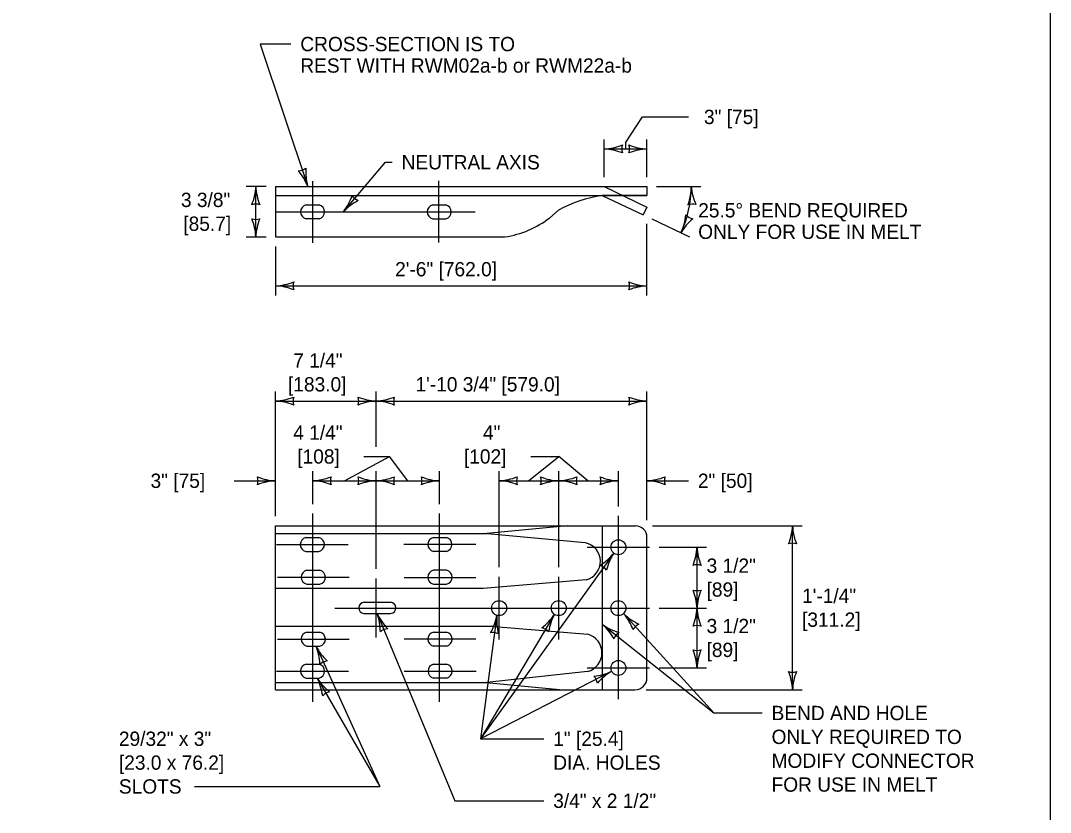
# Model space of a CAD drawing. Extents: x 49991.4 to 50021, y 49987.6 to 50011.4.
# Drawn here: x 50004.296 to 50008.615, y 50002.547 to 50005.867 of the extents above; entities that cross this region are included whole.
import ezdxf

# ---------------------------------------------------------------- set-up
doc = ezdxf.new("R2010")
doc.units = 0
for name, color, linetype in [('Level 1', 7, 'Continuous'), ('Level 2', 7, 'Continuous'), ('Level 3', 7, 'Continuous'), ('Level 4', 7, 'Continuous'), ('Level 5', 7, 'Continuous')]:
    doc.layers.add(name, color=color, linetype=linetype)

msp = doc.modelspace()

# ---------------------------------------------------------------- linework, layer by layer
at = {"layer": 'Level 1'}
for p, q in [((50005.3649, 50005.1705), (50006.9227, 50005.1705)), ((50005.3649, 50005.1705), (50005.3649, 50004.9596)), ((50006.9227, 50005.1705), (50006.9227, 50005.134)), ((50006.9227, 50005.134), (50006.7352, 50005.134)), ((50005.4929, 50005.0942), (50005.5474, 50005.0942)), ((50006.0241, 50005.0943), (50006.0787, 50005.0943)), ((50006.5147, 50005.0402), (50006.551, 50005.0713)), ((50005.5476, 50005.0356), (50005.4927, 50005.0356)), ((50006.024, 50005.0357), (50006.0788, 50005.0357)), ((50005.3649, 50004.9596), (50006.327, 50004.9596)), ((50005.3651, 50003.0612), (50005.3651, 50003.7485)), ((50005.3651, 50003.7485), (50006.8742, 50003.7485)), ((50006.5889, 50003.7485), (50006.2508, 50003.7166)), ((50005.3651, 50003.7166), (50006.2508, 50003.7166)), ((50005.492, 50003.6994), (50005.5465, 50003.6994)), ((50006.0268, 50003.6995), (50006.0267, 50003.6995)), ((50006.0267, 50003.6995), (50006.0814, 50003.6995)), ((50006.6641, 50003.6776), (50006.2388, 50003.7166)), ((50006.9227, 50003.1115), (50006.9227, 50003.7)), ((50005.4918, 50003.6408), (50005.5467, 50003.6408)), ((50006.0815, 50003.6409), (50006.0267, 50003.6409)), ((50005.4961, 50003.5619), (50005.5506, 50003.5619)), ((50006.0819, 50003.562), (50006.0272, 50003.562)), ((50006.2352, 50003.4858), (50005.3651, 50003.4858)), ((50005.4959, 50003.5033), (50005.5508, 50003.5033)), ((50006.0272, 50003.5034), (50006.082, 50003.5034)), ((50006.6677, 50003.5213), (50006.2352, 50003.4858)), ((50005.7369, 50003.4276), (50005.8463, 50003.4276)), ((50005.7356, 50003.3808), (50005.8475, 50003.3808)), ((50006.2836, 50003.3257), (50005.3651, 50003.3257)), ((50006.2836, 50003.3257), (50006.6741, 50003.2936)), ((50005.4961, 50003.3026), (50005.5506, 50003.3026)), ((50006.0272, 50003.3027), (50006.0819, 50003.3027)), ((50005.4959, 50003.244), (50005.5508, 50003.244)), ((50006.082, 50003.2441), (50006.0272, 50003.2441)), ((50006.0272, 50003.2441), (50006.0273, 50003.2441)), ((50005.4928, 50003.1685), (50005.5475, 50003.1685)), ((50006.0277, 50003.1684), (50006.0277, 50003.1684)), ((50006.0277, 50003.1684), (50006.0823, 50003.1684)), ((50006.6738, 50003.1373), (50006.2508, 50003.0916)), ((50005.4927, 50003.1099), (50005.5475, 50003.1099)), ((50006.0824, 50003.1098), (50006.0275, 50003.1098)), ((50005.3651, 50003.0916), (50006.2508, 50003.0916)), ((50005.3651, 50003.0612), (50006.8724, 50003.0612)), ((50006.5561, 50003.0612), (50006.2341, 50003.0916))]:
    msp.add_line(p, q, dxfattribs=at)
msp.add_lwpolyline([(50008.6146, 50011.2628), (50000.3356, 50011.2628), (50000.3356, 50000.0624), (50008.6146, 50000.0624)], close=True, dxfattribs=at)
for centre in [(50006.8026, 50003.6586), (50006.3026, 50003.4032), (50006.5526, 50003.4032), (50006.8026, 50003.4032), (50006.8026, 50003.1526)]:
    msp.add_circle(centre, 0.0313, dxfattribs=at)
for centre, radius, start, end in [((50006.8256, 50004.5662), 0.5749, 99.0478, 118.5325), ((50005.4994, 50005.0649), 0.03, 102.6034, 256.9962), ((50005.5408, 50005.0649), 0.03, 283.0068, 77.3935), ((50006.0307, 50005.065), 0.03, 102.7122, 257.1026), ((50006.0721, 50005.065), 0.03, 282.9005, 77.2847), ((50006.2644, 50005.3642), 0.4094, 278.786, 307.682), ((50006.8742, 50003.7), 0.0485, 0, 90), ((50005.4985, 50003.6701), 0.03, 102.6034, 256.9962), ((50005.5399, 50003.6701), 0.03, 283.0068, 77.3935), ((50006.0334, 50003.6702), 0.03, 102.7122, 257.1026), ((50006.0748, 50003.6702), 0.03, 282.9005, 77.2847), ((50006.647, 50003.599), 0.0804, 284.9666, 77.7099), ((50005.5026, 50003.5326), 0.03, 102.6034, 256.9962), ((50005.544, 50003.5326), 0.03, 283.0068, 77.3935), ((50006.0339, 50003.5327), 0.03, 102.7122, 257.1026), ((50006.0753, 50003.5327), 0.03, 282.9005, 77.2847), ((50005.7369, 50003.4042), 0.0234, 89.9951, 266.7585), ((50005.8463, 50003.4042), 0.0234, 272.9074, 89.9976), ((50005.5026, 50003.2733), 0.03, 102.6034, 256.9962), ((50005.544, 50003.2733), 0.03, 283.0068, 77.3935), ((50006.0339, 50003.2734), 0.03, 102.7122, 257.1026), ((50006.0753, 50003.2734), 0.03, 282.9005, 77.2847), ((50006.6528, 50003.2155), 0.081, 285.0418, 74.706), ((50005.4994, 50003.1392), 0.03, 102.7902, 257.18), ((50005.5408, 50003.1392), 0.03, 282.8231, 77.2067), ((50006.0343, 50003.1391), 0.03, 102.6821, 257.073), ((50006.0757, 50003.1391), 0.03, 282.9301, 77.3148), ((50006.8724, 50003.1115), 0.0503, 270, 0)]:
    msp.add_arc(centre, radius, start, end, dxfattribs=at)
at = {"layer": 'Level 3'}
for p, q in [((50005.4287, 50005.7684), (50005.301, 50005.7684)), ((50005.301, 50005.7684), (50005.5002, 50005.1705)), ((50006.833, 50005.3544), (50006.9041, 50005.463)), ((50006.9041, 50005.463), (50007.0974, 50005.463)), ((50006.7433, 50005.2105), (50006.7433, 50005.3687)), ((50006.833, 50005.3544), (50006.833, 50005.3287)), ((50006.9227, 50005.2105), (50006.9227, 50005.3687)), ((50006.7433, 50005.3287), (50006.9227, 50005.3287)), ((50005.6496, 50005.065), (50005.8263, 50005.2729)), ((50005.8263, 50005.2729), (50005.8535, 50005.2729)), ((50005.3249, 50005.1705), (50005.2421, 50005.1705)), ((50005.2821, 50004.9597), (50005.2821, 50005.1705)), ((50006.9627, 50005.1705), (50007.1485, 50005.1705)), ((50006.9227, 50004.7144), (50006.9227, 50005.0153)), ((50006.9431, 50005.0349), (50007.1008, 50004.9597)), ((50005.2421, 50004.9597), (50005.3249, 50004.9597)), ((50005.3649, 50004.9196), (50005.3649, 50004.7144)), ((50005.3649, 50004.7544), (50006.9227, 50004.7544)), ((50005.3649, 50003.7885), (50005.3649, 50004.3117)), ((50005.787, 50004.0791), (50005.787, 50004.3117)), ((50006.9227, 50003.7717), (50006.9227, 50004.3117)), ((50005.3649, 50004.2717), (50005.787, 50004.2717)), ((50005.787, 50004.2717), (50006.9227, 50004.2717)), ((50005.6542, 50003.9373), (50005.8426, 50004.0391)), ((50005.7358, 50004.0391), (50005.8426, 50004.0391)), ((50005.9198, 50003.9373), (50005.8426, 50004.0391)), ((50006.4264, 50003.9373), (50006.5526, 50004.0391)), ((50006.4349, 50004.0391), (50006.5526, 50004.0391)), ((50006.6748, 50003.9373), (50006.5526, 50004.0391)), ((50005.5215, 50003.8394), (50005.5215, 50003.9773)), ((50005.787, 50003.5676), (50005.787, 50003.9773)), ((50006.0526, 50003.8395), (50006.0526, 50003.9773)), ((50006.3026, 50003.5745), (50006.3026, 50003.9773)), ((50006.5526, 50003.5745), (50006.5526, 50003.9773)), ((50006.8026, 50003.8299), (50006.8026, 50003.9773)), ((50005.1916, 50003.9373), (50005.3649, 50003.9373)), ((50005.5215, 50003.9373), (50005.787, 50003.9373)), ((50005.787, 50003.9373), (50006.0526, 50003.9373)), ((50006.3026, 50003.9373), (50006.5526, 50003.9373)), ((50006.5526, 50003.9373), (50006.8026, 50003.9373)), ((50006.9227, 50003.9373), (50007.0961, 50003.9373)), ((50006.9459, 50003.7485), (50007.573, 50003.7485)), ((50007.533, 50003.0612), (50007.533, 50003.7485)), ((50006.9739, 50003.6586), (50007.1725, 50003.6586)), ((50007.1325, 50003.404), (50007.1325, 50003.6586)), ((50006.7831, 50003.6341), (50006.2238, 50002.8556)), ((50006.9739, 50003.4032), (50007.1725, 50003.4032)), ((50007.1325, 50003.1526), (50007.1325, 50003.404)), ((50005.7907, 50003.3808), (50006.1171, 50002.5956)), ((50006.5344, 50003.3777), (50006.2238, 50002.8556)), ((50006.2935, 50003.3733), (50006.2238, 50002.8556)), ((50006.8247, 50003.3811), (50007.2032, 50002.9636)), ((50006.7352, 50003.3354), (50007.2032, 50002.9636)), ((50005.5347, 50003.244), (50005.8027, 50002.6556)), ((50006.7748, 50003.1383), (50006.2238, 50002.8556)), ((50006.9739, 50003.1526), (50007.1725, 50003.1526)), ((50005.5389, 50003.1099), (50005.8027, 50002.6556)), ((50006.9187, 50003.0612), (50007.573, 50003.0612)), ((50007.2032, 50002.9636), (50007.4051, 50002.9636)), ((50006.2238, 50002.8556), (50006.4894, 50002.8556)), ((50005.0246, 50002.6556), (50005.8027, 50002.6556)), ((50006.1171, 50002.5956), (50006.4894, 50002.5956))]:
    msp.add_line(p, q, dxfattribs=at)
for centre, radius, start, end in [((50006.7341, 50005.5508), 0.2223, 272.3605, 292.544), ((50006.8715, 50005.3287), 0.0548, 162.1388, 197.8612), ((50006.9319, 50005.5508), 0.2223, 247.456, 267.6395), ((50006.7945, 50005.3287), 0.0548, 342.1388, 17.8612), ((50006.7318, 50005.096), 0.233, 67.9228, 87.1727), ((50006.9342, 50005.096), 0.233, 92.8273, 112.0772), ((50005.4597, 50005.2921), 0.0548, 270.5738, 306.2961), ((50005.2831, 50005.086), 0.233, 21.2623, 40.5121), ((50005.7138, 50005.2321), 0.2223, 175.891, 196.0745), ((50005.06, 50005.1797), 0.2223, 337.456, 357.6395), ((50005.5148, 50005.182), 0.233, 182.8273, 202.0772), ((50006.6585, 50005.1705), 0.45, 334.5194, 0.0004), ((50006.8862, 50005.1719), 0.2223, 339.456, 359.6395), ((50007.3407, 50005.1901), 0.233, 184.8273, 204.0772), ((50005.4648, 50005.207), 0.233, 322.4652, 341.715), ((50005.7326, 50005.1627), 0.0548, 211.7767, 247.499), ((50005.2821, 50005.0423), 0.0548, 72.1388, 107.8612), ((50005.8129, 50004.9142), 0.2223, 117.0939, 137.2774), ((50007.113, 50005.0424), 0.0548, 74.1388, 109.8612), ((50006.8643, 50005.0731), 0.2223, 334.3605, 354.544), ((50007.1249, 50005.0901), 0.0548, 224.1388, 259.8612), ((50005.2821, 50005.0879), 0.0548, 252.1388, 287.8612), ((50005.0494, 50004.9482), 0.233, 2.8273, 22.0772), ((50005.5042, 50004.9505), 0.2223, 157.456, 177.6395), ((50007.2648, 50004.8575), 0.233, 129.9228, 149.1727), ((50005.3534, 50004.9871), 0.233, 272.8273, 292.0772), ((50005.3557, 50004.5323), 0.2223, 67.456, 87.6395), ((50005.4931, 50004.7544), 0.0548, 162.1388, 197.8612), ((50006.9319, 50004.9765), 0.2223, 247.456, 267.6395), ((50006.7945, 50004.7544), 0.0548, 342.1388, 17.8612), ((50006.9342, 50004.5217), 0.233, 92.8273, 112.0772), ((50005.3534, 50004.5044), 0.233, 272.8273, 292.0772), ((50005.3557, 50004.0496), 0.2223, 67.456, 87.6395), ((50005.4931, 50004.2717), 0.0548, 162.1388, 197.8612), ((50005.7962, 50004.4938), 0.2223, 247.456, 267.6395), ((50005.6588, 50004.2717), 0.0548, 342.1388, 17.8612), ((50005.7985, 50004.039), 0.233, 92.8273, 112.0772), ((50005.7755, 50004.5044), 0.233, 272.8273, 292.0772), ((50005.7778, 50004.0496), 0.2223, 67.456, 87.6395), ((50005.9152, 50004.2717), 0.0548, 162.1388, 197.8612), ((50006.9319, 50004.4938), 0.2223, 247.456, 267.6395), ((50006.7945, 50004.2717), 0.0548, 342.1388, 17.8612), ((50006.9342, 50004.039), 0.233, 92.8273, 112.0772), ((50005.3741, 50004.1594), 0.2223, 247.456, 267.6395), ((50005.2367, 50003.9373), 0.0548, 342.1388, 17.8612), ((50005.3764, 50003.7046), 0.233, 92.8273, 112.0772), ((50005.51, 50004.17), 0.233, 272.8273, 292.0772), ((50005.5123, 50003.7152), 0.2223, 67.456, 87.6395), ((50005.6497, 50003.9373), 0.0548, 162.1388, 197.8612), ((50005.7962, 50004.1594), 0.2223, 247.456, 267.6395), ((50005.6588, 50003.9373), 0.0548, 342.1388, 17.8612), ((50005.7985, 50003.7046), 0.233, 92.8273, 112.0772), ((50005.7755, 50004.17), 0.233, 272.8273, 292.0772), ((50005.7778, 50003.7152), 0.2223, 67.456, 87.6395), ((50005.9152, 50003.9373), 0.0548, 162.1388, 197.8612), ((50006.0618, 50004.1594), 0.2223, 247.456, 267.6395), ((50005.9244, 50003.9373), 0.0548, 342.1388, 17.8612), ((50006.0641, 50003.7046), 0.233, 92.8273, 112.0772), ((50006.2911, 50004.17), 0.233, 272.8273, 292.0772), ((50006.2934, 50003.7152), 0.2223, 67.456, 87.6395), ((50006.4308, 50003.9373), 0.0548, 162.1388, 197.8612), ((50006.5618, 50004.1594), 0.2223, 247.456, 267.6395), ((50006.4244, 50003.9373), 0.0548, 342.1388, 17.8612), ((50006.5641, 50003.7046), 0.233, 92.8273, 112.0772), ((50006.5411, 50004.17), 0.233, 272.8273, 292.0772), ((50006.5434, 50003.7152), 0.2223, 67.456, 87.6395), ((50006.6808, 50003.9373), 0.0548, 162.1388, 197.8612), ((50006.8118, 50004.1594), 0.2223, 247.456, 267.6395), ((50006.6744, 50003.9373), 0.0548, 342.1388, 17.8612), ((50006.8141, 50003.7046), 0.233, 92.8273, 112.0772), ((50006.9112, 50004.17), 0.233, 272.8273, 292.0772), ((50006.9135, 50003.7152), 0.2223, 67.456, 87.6395), ((50007.0509, 50003.9373), 0.0548, 162.1388, 197.8612), ((50007.3109, 50003.7577), 0.2223, 337.456, 357.6395), ((50007.7657, 50003.76), 0.233, 182.8273, 202.0772), ((50006.9104, 50003.6678), 0.2223, 337.456, 357.6395), ((50007.3652, 50003.6701), 0.233, 182.8273, 202.0772), ((50007.533, 50003.6203), 0.0548, 72.1388, 107.8612), ((50006.6073, 50003.7702), 0.2223, 302.0762, 322.2597), ((50006.9795, 50003.5087), 0.233, 147.4475, 166.6974), ((50006.7089, 50003.5296), 0.0548, 36.759, 72.4814), ((50007.1325, 50003.5304), 0.0548, 72.1388, 107.8612), ((50007.1325, 50003.5314), 0.0548, 252.1388, 287.8612), ((50006.8998, 50003.3917), 0.233, 2.8273, 22.0772), ((50007.3546, 50003.394), 0.2223, 157.456, 177.6395), ((50006.9104, 50003.4124), 0.2223, 337.456, 357.6395), ((50007.3652, 50003.4147), 0.233, 182.8273, 202.0772), ((50005.5821, 50003.304), 0.2223, 0.0269, 20.2104), ((50006.0012, 50003.4807), 0.233, 205.3982, 224.648), ((50006.0747, 50003.4125), 0.2223, 329.6392, 349.8227), ((50006.5256, 50003.353), 0.233, 175.0105, 194.2603), ((50006.3476, 50003.4983), 0.2223, 306.976, 327.1595), ((50006.7408, 50003.2696), 0.233, 152.3473, 171.5972), ((50006.6542, 50003.2384), 0.2223, 19.7202, 39.9037), ((50006.9892, 50003.5461), 0.233, 225.0915, 244.3414), ((50005.8399, 50003.2624), 0.0548, 94.7097, 130.432), ((50006.4694, 50003.2672), 0.0548, 41.6588, 77.3812), ((50006.5899, 50003.1671), 0.2223, 28.9916, 49.1751), ((50006.871, 50003.5247), 0.233, 234.3629, 253.6128), ((50006.911, 50003.2862), 0.0548, 114.403, 150.1254), ((50007.1325, 50003.275), 0.0548, 72.1388, 107.8612), ((50006.276, 50003.2462), 0.0548, 64.322, 100.0444), ((50006.8356, 50003.2556), 0.0548, 123.6744, 159.3968), ((50005.3287, 50003.1603), 0.2223, 1.9416, 22.1252), ((50005.7417, 50003.3509), 0.233, 207.3129, 226.5628), ((50007.1325, 50003.2808), 0.0548, 252.1388, 287.8612), ((50006.8998, 50003.1411), 0.233, 2.8273, 22.0772), ((50007.3546, 50003.1434), 0.2223, 157.456, 177.6395), ((50005.5878, 50003.1273), 0.0548, 96.6245, 132.3468), ((50006.6808, 50003.3398), 0.2223, 274.8189, 295.0024), ((50006.8919, 50002.9369), 0.233, 120.1902, 139.44), ((50007.533, 50003.1894), 0.0548, 252.1388, 287.8612), ((50007.3003, 50003.0497), 0.233, 2.8273, 22.0772), ((50007.7552, 50003.052), 0.2223, 157.456, 177.6395), ((50005.3422, 50003.0063), 0.2223, 7.6025, 27.786), ((50005.7344, 50003.2367), 0.233, 212.9738, 232.2236), ((50006.6609, 50003.0794), 0.0548, 9.5017, 45.2241), ((50005.6033, 50002.999), 0.0548, 102.2853, 138.0076)]:
    msp.add_arc(centre, radius, start, end, dxfattribs=at)
at = {"layer": 'Level 4'}
for p, q in [((50006.7433, 50005.1705), (50006.9227, 50005.085)), ((50005.3649, 50005.134), (50006.9227, 50005.134)), ((50006.7352, 50005.134), (50006.907, 50005.0521)), ((50006.9227, 50005.085), (50006.907, 50005.0521)), ((50006.7352, 50003.7485), (50006.7352, 50003.0612))]:
    msp.add_line(p, q, dxfattribs=at)
at = {"layer": 'Level 5'}
for p, q in [((50005.5206, 50004.9356), (50005.5206, 50005.1942)), ((50006.0503, 50004.9357), (50006.0503, 50005.1943)), ((50005.3694, 50005.065), (50006.2021, 50005.065)), ((50005.5214, 50003.0099), (50005.5214, 50003.7994)), ((50006.0526, 50003.0098), (50006.0526, 50003.7995)), ((50006.8026, 50003.0213), (50006.8026, 50003.7899)), ((50005.3685, 50003.6701), (50005.67, 50003.6701)), ((50005.9033, 50003.6714), (50006.2048, 50003.6714)), ((50006.6713, 50003.6586), (50006.9339, 50003.6586)), ((50005.3726, 50003.5326), (50005.6741, 50003.5326)), ((50005.787, 50003.2808), (50005.787, 50003.5276)), ((50005.9038, 50003.5315), (50006.2053, 50003.5315)), ((50006.3026, 50003.2719), (50006.3026, 50003.5345)), ((50006.5526, 50003.2719), (50006.5526, 50003.5345)), ((50005.6135, 50003.4032), (50006.9339, 50003.4032)), ((50005.3726, 50003.2733), (50005.6741, 50003.2733)), ((50005.9038, 50003.2746), (50006.2053, 50003.2746)), ((50005.3694, 50003.1392), (50005.6709, 50003.1392)), ((50005.9042, 50003.1394), (50006.2057, 50003.1394)), ((50006.6713, 50003.1526), (50006.9339, 50003.1526))]:
    msp.add_line(p, q, dxfattribs=at)

# ---------------------------------------------------------------- texts
at = {"layer": 'Level 2'}
for s, p in [('CROSS-SECTION IS TO', (50005.4687, 50005.7384)), ('REST WITH RWM02a-b or RWM22a-b', (50005.4687, 50005.6484)), ('3" [75]', (50007.1616, 50005.433)), ('NEUTRAL AXIS', (50005.8935, 50005.2429)), ('3 3/8"', (50004.968, 50005.0851)), ('25.5° BEND REQUIRED', (50007.1374, 50005.0413)), ('[85.7]', (50004.978, 50004.9851)), ('ONLY FOR USE IN MELT', (50007.1374, 50004.9513)), ('2\'-6" [762.0]', (50005.8663, 50004.7944)), ('7 1/4"', (50005.4389, 50004.4117)), ('[183.0]', (50005.417, 50004.3117)), ('1\'-10 3/4" [579.0]', (50005.9518, 50004.3117)), ('4 1/4"', (50005.439, 50004.1091)), ('4"', (50006.2348, 50004.1091)), ('[108]', (50005.4559, 50004.0091)), ('[102]', (50006.1549, 50004.0091)), ('3" [75]', (50004.8405, 50003.9073)), ('2" [50]', (50007.1361, 50003.9073)), ('3 1/2"', (50007.1725, 50003.5513)), ('[89]', (50007.1725, 50003.4513)), ('1\'-1/4"', (50007.573, 50003.4249)), ('3 1/2"', (50007.1725, 50003.2983)), ('[311.2]', (50007.573, 50003.3249)), ('[89]', (50007.1725, 50003.1983)), ('BEND AND HOLE', (50007.4451, 50002.9336)), ('29/32" x 3"', (50004.7078, 50002.8256)), ('1" [25.4]', (50006.5294, 50002.8256)), ('ONLY REQUIRED TO', (50007.4451, 50002.8336)), ('MODIFY CONNECTOR', (50007.4451, 50002.7336)), ('[23.0 x 76.2]', (50004.7078, 50002.7256)), ('DIA. HOLES', (50006.5294, 50002.7256)), ('SLOTS', (50004.7078, 50002.6256)), ('FOR USE IN MELT', (50007.4451, 50002.6336)), ('3/4" x 2 1/2"', (50006.5294, 50002.5656))]:
    msp.add_text(s, height=0.06, dxfattribs=at).set_placement(p)

doc.saveas('drawing.dxf')
